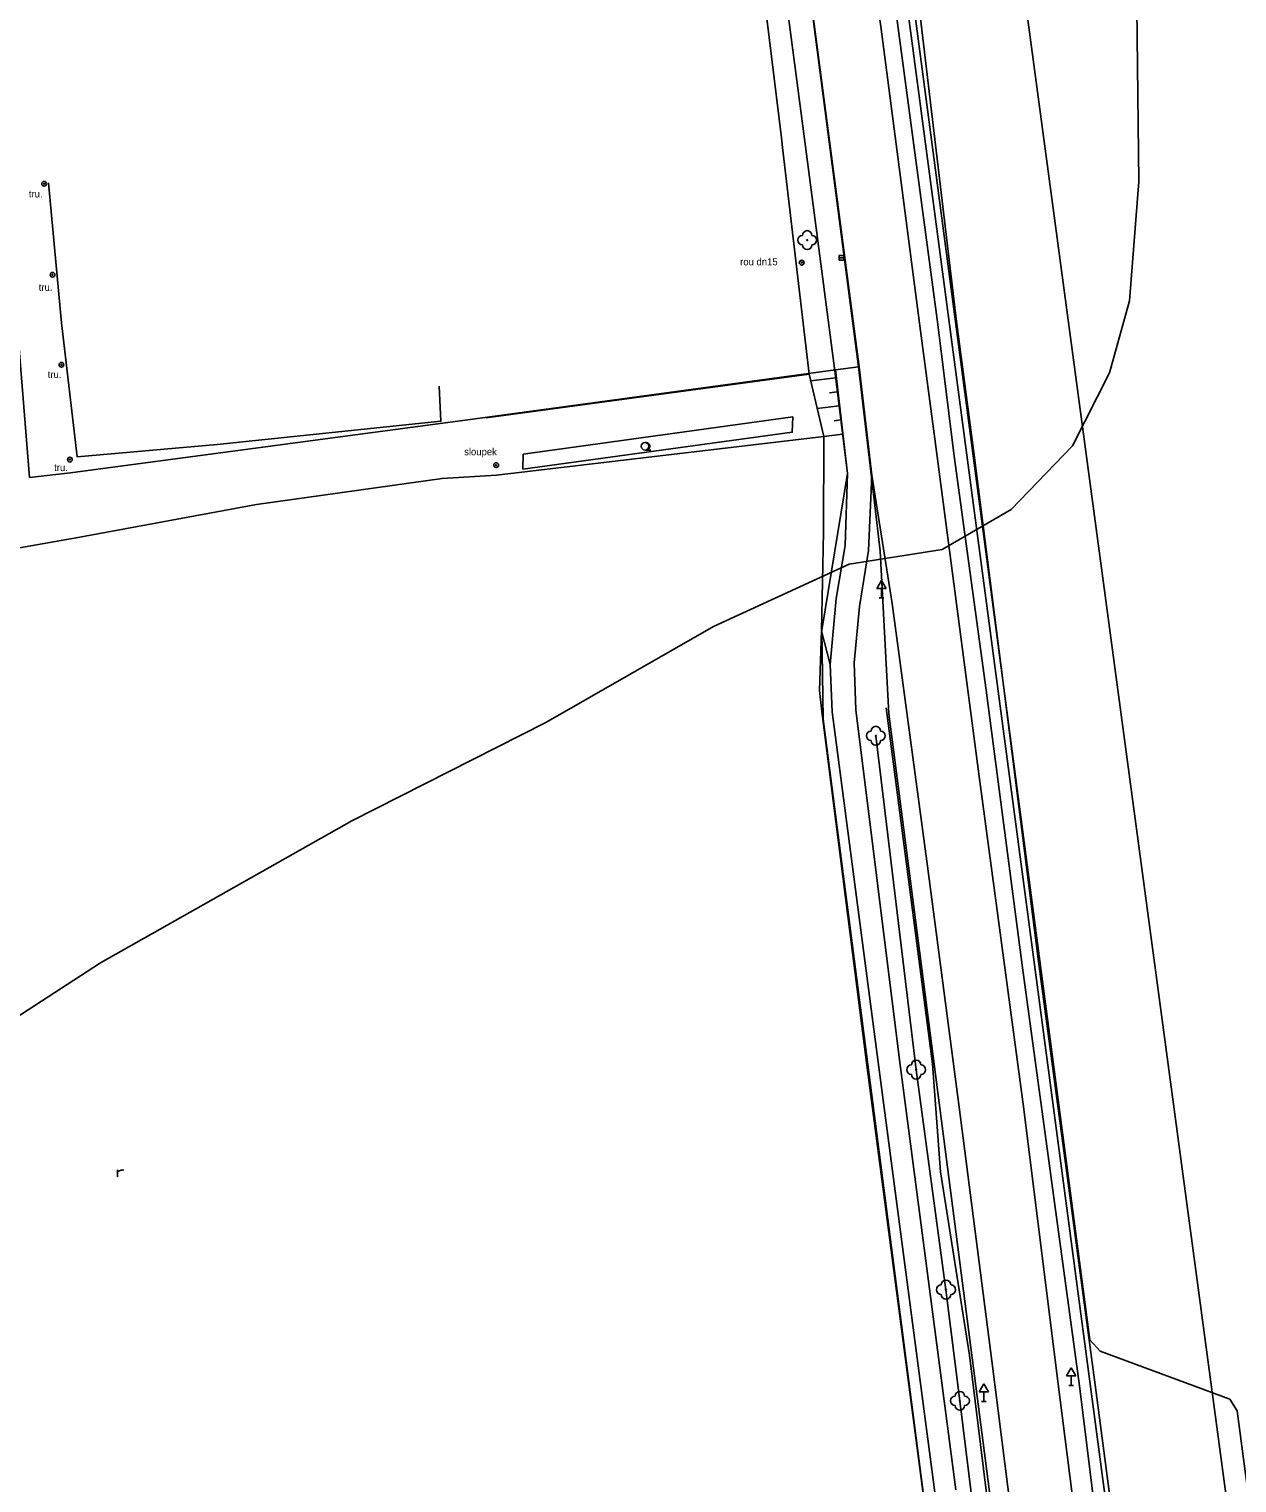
# Model space of a CAD drawing. Extents: x -555887 to -552101, y -1100251 to -1096546.
# Drawn here: x -554088.5 to -553960.9, y -1098102.3 to -1097948.7 of the extents above; entities that cross this region are included whole.
import ezdxf

# ---------------------------------------------------------------- set-up
doc = ezdxf.new("R2010")
doc.units = 0
for name, color, linetype in [('07_KANALIZACE', 7, 'Continuous'), ('07_VODOVOD', 7, 'Continuous'), ('PARCELY_silnice', 7, 'Continuous'), ('vrstevnice', 7, 'Continuous'), ('ZSST', 7, 'Continuous'), ('zájem', 7, 'Continuous')]:
    doc.layers.add(name, color=color, linetype=linetype)

msp = doc.modelspace()

# ---------------------------------------------------------------- linework, layer by layer
at = {"layer": '07_KANALIZACE'}
msp.add_lwpolyline([(-553933.89, -1098299.13), (-553960.89, -1098094.71), (-553961.69, -1098093.49), (-553975.36, -1098088.42), (-553976.47, -1098087.2), (-553997.02, -1097931.32), (-553999.16, -1097907.75), (-553999.72, -1097884.17), (-554000.63, -1097884.27), (-554001.15, -1097883.39), (-554017.16, -1097885.22), (-554171.94, -1097905.19), (-554183.71, -1097906.5), (-554193.28, -1097906.43), (-554202.55, -1097905.69), (-554209.22, -1097906.28), (-554215.09, -1097906.8), (-554226.01, -1097910.87), (-554237.13, -1097913.33)], dxfattribs=at)
at = {"layer": '07_VODOVOD'}
msp.add_lwpolyline([(-553936.18, -1098296.39), (-554003.21, -1097797.26), (-554016.58, -1097798.55), (-554021.42, -1097763.29), (-554007.81, -1097761.46), (-554017.88, -1097690.59), (-554019.47, -1097678.04), (-553931.71, -1097666.8), (-553860.51, -1097660.95), (-553851.19, -1097659.98), (-553809.18, -1097658.76), (-553772.31, -1097657.57), (-553745.69, -1097656.81), (-553714.89, -1097655.5), (-553705.57, -1097655.38), (-553663.41, -1097654.21), (-553621.83, -1097652.81), (-553564.87, -1097648.3)], dxfattribs=at)
at = {"layer": 'PARCELY_silnice'}
for points in [[(-553950.34, -1098288.41), (-554001.81, -1097900.62), (-554000.01, -1097890.44), (-554002.33, -1097872.53), (-554008.3, -1097844.49), (-554029.64, -1097687.62), (-554030.91, -1097678.33), (-554047.02, -1097559.88)], [(-554053.21, -1097604.42), (-554046.53, -1097659.36), (-554040.57, -1097685.1), (-554037.19, -1097711.74), (-554032.71, -1097743.24), (-554030.08, -1097764.38), (-554029.42, -1097766.27), (-554026.13, -1097796.62), (-554021.75, -1097825.43), (-554018.68, -1097848.98), (-554014.41, -1097881.75), (-554013.24, -1097889.61), (-554000.89, -1097984.42), (-553998.62, -1098003.87), (-553997.67, -1098021.07), (-553963.01, -1098289.11)]]:
    msp.add_lwpolyline(points, dxfattribs=at)
msp.add_lwpolyline([(-553975.92, -1098339.86), (-553969.49, -1098341.12), (-553964.35, -1098318.47), (-553963.01, -1098289.11), (-553997.67, -1098021.07), (-553998.62, -1098003.87), (-554000.89, -1097984.42), (-554003.33, -1097984.74), (-554002.07, -1097995.68), (-554004.77, -1098012.25), (-554004.64, -1098021.66), (-553970.02, -1098289.25), (-553971.01, -1098316.82)], close=True, dxfattribs=at)
at = {"layer": 'vrstevnice'}
msp.add_lwpolyline([(-554220.66, -1098097.94), (-554208.86, -1098100.05), (-554185.27, -1098101.59), (-554176.57, -1098101.45), (-554168.14, -1098099.63), (-554156.63, -1098095.69), (-554138.09, -1098086.43), (-554136.41, -1098084.88), (-554131.64, -1098082.36), (-554110.85, -1098066.77), (-554080.95, -1098047.39), (-554054.41, -1098032.37), (-554033.91, -1098021.98), (-554016.21, -1098011.87), (-554001.89, -1098005.27), (-553992.06, -1098003.72), (-553984.76, -1097999.51), (-553978.3, -1097992.77), (-553974.37, -1097985.05), (-553972.26, -1097977.47), (-553971.28, -1097964.83), (-553971.56, -1097940.4), (-553970.86, -1097921.02)], dxfattribs=at)
at = {"layer": 'ZSST'}
for p, q in [((-554011.92, -1097936.34), (-554009.04, -1097960.25)), ((-554008.91, -1097961.26), (-554009.04, -1097960.25)), ((-554002.94, -1097972.92), (-554002.44, -1097972.92)), ((-554003.4, -1097984.84), (-554003.4, -1097984.84)), ((-554004.55, -1097991.77), (-554006.09, -1097985.19)), ((-554003.31, -1097985.57), (-554005.93, -1097985.89)), ((-554003.13, -1097987.06), (-554003.94, -1097987.16)), ((-554002.94, -1097988.55), (-554005.24, -1097988.83)), ((-554002.76, -1097990.04), (-554003.47, -1097990.13)), ((-554004.55, -1097991.77), (-554039.12, -1097995.88)), ((-554002.58, -1097991.53), (-554004.55, -1097991.77)), ((-554023.43, -1097993.22), (-554023.33, -1097993.22)), ((-554023.33, -1097993.22), (-554022.83, -1097993.22)), ((-553999.82, -1098003.82), (-553999.5, -1097995.87)), ((-553998.97, -1098007.83), (-553998.47, -1098006.98)), ((-553998.97, -1098007.83), (-553997.97, -1098007.83)), ((-553998.47, -1098006.98), (-553997.97, -1098007.83)), ((-553998.47, -1098008.83), (-553998.47, -1098007.83)), ((-553998.72, -1098008.83), (-553998.22, -1098008.83)), ((-554003.88, -1098015.88), (-554004.8, -1098012.3)), ((-553978.93, -1098091.02), (-553978.43, -1098090.17)), ((-553978.93, -1098091.02), (-553977.93, -1098091.02)), ((-553978.43, -1098090.17), (-553977.93, -1098091.02)), ((-553978.43, -1098092.02), (-553978.43, -1098091.02)), ((-553988.16, -1098092.71), (-553987.66, -1098091.86)), ((-553987.66, -1098091.86), (-553987.16, -1098092.71)), ((-553978.68, -1098092.02), (-553978.18, -1098092.02)), ((-553988.16, -1098092.71), (-553987.16, -1098092.71)), ((-553987.91, -1098093.71), (-553987.41, -1098093.71)), ((-553987.66, -1098093.71), (-553987.66, -1098092.71))]:
    msp.add_line(p, q, dxfattribs=at)
for points in [[(-553988.71, -1097993.49), (-553990.53, -1097979.62), (-553994.29, -1097948.23), (-553997.94, -1097915.23), (-553998.81, -1097902.59), (-553998.52, -1097895.24), (-553994.86, -1097892.14), (-553987.27, -1097890.96), (-553987.98, -1097886.25), (-553996.36, -1097886.64), (-553999.4, -1097885.09), (-554001.76, -1097874.55)], [(-554014.9, -1097898.08), (-554013.96, -1097906.04), (-554012.3, -1097916.37), (-554009.4, -1097938.89), (-554006.77, -1097959.01), (-554003.4, -1097984.84)], [(-554004.38, -1097907.95), (-553998.53, -1097948.46), (-553994.33, -1097980.61), (-553992.57, -1097993.91)], [(-553990.78, -1097993.85), (-553992.5, -1097979.96), (-553996.76, -1097948.12), (-554002.05, -1097908.06)], [(-554004.21, -1097958.68), (-554006.85, -1097938.54), (-554009.57, -1097915.75), (-554009.89, -1097915.72)], [(-553999.5, -1097995.87), (-554000.83, -1097984.42), (-554004.21, -1097958.68)], [(-554008.91, -1097961.26), (-554006.09, -1097985.19), (-554040.22, -1097989.81)], [(-554045.19, -1097986.48), (-554044.99, -1097990.17), (-554068.61, -1097992.64), (-554083.41, -1097993.95), (-554085.05, -1097979.79), (-554086.43, -1097964.99)], [(-554152.46, -1098196.01), (-554156.99, -1098165.3), (-554161, -1098137.92), (-554165.48, -1098109.51), (-554170.05, -1098075.75), (-554174.2, -1098049.14), (-554157.63, -1098045.66), (-554138.38, -1098042.46), (-554114.45, -1098037.99), (-554118.53, -1098007.72), (-554123.48, -1097972.27), (-554107.54, -1097970.66), (-554103.52, -1097970.92), (-554100.42, -1097986.55), (-554097.93, -1098005.02), (-554083.5, -1098002.49), (-554064.47, -1097998.97), (-554044.87, -1097996.23), (-554039.12, -1097995.88)], [(-554002.31, -1098003.31), (-554002.07, -1097995.68), (-554003.4, -1097984.84)], [(-553977.31, -1098339.19), (-553975.61, -1098335.29), (-553972.59, -1098323.6), (-553971.44, -1098316.97), (-553969.88, -1098303.44), (-553969.81, -1098290.61), (-553972.17, -1098269.21), (-553975.16, -1098246.95), (-553978.59, -1098220.4), (-553983.45, -1098184.31), (-553986.7, -1098159.44), (-553989.55, -1098137.24), (-553994, -1098104), (-554000.05, -1098057.93), (-554004.75, -1098020.85), (-554005.01, -1098018.62), (-554004.8, -1098012.3), (-554004.6, -1098001.9), (-554004.55, -1097991.77)], [(-553973.87, -1098138.69), (-553979.61, -1098093.26), (-553983.51, -1098062.31), (-553988.15, -1098027.7), (-553992.57, -1097993.91)], [(-553951.2, -1098319.93), (-553951.28, -1098302.07), (-553958.7, -1098233.53), (-553961.27, -1098215.25), (-553968.42, -1098161.7), (-553973.37, -1098125.99), (-553977.56, -1098092.07), (-553983.59, -1098047.63), (-553987.39, -1098018.59), (-553990.78, -1097993.85)], [(-553988.71, -1097993.49), (-553985.58, -1098018.09), (-553981.87, -1098047.25), (-553975.9, -1098091.95), (-553971.51, -1098125.49), (-553966.51, -1098161.83), (-553959.93, -1098205.07), (-553958.71, -1098213.37), (-553956.01, -1098234), (-553950.44, -1098275.83), (-553949.64, -1098302.75), (-553950.51, -1098313.18), (-553948.45, -1098323.92)], [(-553999.5, -1097995.87), (-553997.34, -1098009.41), (-553993.61, -1098037.17), (-553990.25, -1098062.63), (-553986.8, -1098089.44), (-553984.76, -1098105.56), (-553980.36, -1098139.56)], [(-554002.31, -1098003.31), (-554003.24, -1098008.91), (-554003.88, -1098015.88), (-554003.67, -1098020.88)], [(-554001.19, -1098020.67), (-554001.35, -1098015.68), (-554000.79, -1098009.73), (-553999.82, -1098003.82)], [(-553997.98, -1098020.44), (-553993.08, -1098058.06), (-553992.23, -1098069.47), (-553989.18, -1098088.83), (-553987.4, -1098103.12), (-553982.63, -1098137.08)], [(-553992.79, -1098103.58), (-553998.8, -1098057.88), (-554003.67, -1098020.88)], [(-554001.19, -1098020.67), (-553996.57, -1098057.62), (-553990.6, -1098103.06)], [(-553999.06, -1098023.4), (-553994.8, -1098058.67), (-553991.65, -1098081.91), (-553990.18, -1098093.65), (-553988.27, -1098109.08), (-553983.19, -1098145.55)], [(-554079.15, -1098069.99), (-554079.15, -1098069.26)], [(-554079.15, -1098069.5), (-554079.04, -1098069.4), (-554078.94, -1098069.34), (-554078.78, -1098069.29), (-554078.63, -1098069.27), (-554078.48, -1098069.26)]]:
    msp.add_lwpolyline(points, dxfattribs=at)
for points in [[(-554002.94, -1097973.17), (-554002.44, -1097973.17), (-554002.44, -1097972.67), (-554002.94, -1097972.67)], [(-554036.3, -1097993.66), (-554007.82, -1097989.72), (-554007.89, -1097991.34), (-554036.33, -1097995.22)]]:
    msp.add_lwpolyline(points, close=True, dxfattribs=at)
for centre, radius in [((-554086.9, -1097965.09), 0.25), ((-554086.9, -1097965.09), 0.05), ((-554006.31, -1097971.04), 0.05), ((-554006.89, -1097973.42), 0.25), ((-554006.89, -1097973.42), 0.05), ((-554086.01, -1097974.7), 0.25), ((-554086.01, -1097974.7), 0.05), ((-554085.08, -1097984.2), 0.25), ((-554085.08, -1097984.2), 0.05), ((-554023.43, -1097992.82), 0.4), ((-554084.18, -1097994.23), 0.25), ((-554084.18, -1097994.23), 0.05), ((-554039.16, -1097994.81), 0.25), ((-554039.16, -1097994.81), 0.05), ((-553999.06, -1098023.4), 0.05), ((-553994.8, -1098058.67), 0.05), ((-553991.65, -1098081.91), 0.05), ((-553990.18, -1098093.65), 0.05)]:
    msp.add_circle(centre, radius, dxfattribs=at)
for centre, radius, start, end in [((-554006.81, -1097971.04), 0.5, 90, 270), ((-554006.31, -1097970.54), 0.5, 0, 180), ((-554005.81, -1097971.04), 0.5, 270, 90), ((-554006.31, -1097971.54), 0.5, 180, 0), ((-554023.33, -1097992.82), 0.4, 259.6952, 97.1808), ((-553999.56, -1098023.4), 0.5, 90, 270), ((-553999.06, -1098022.9), 0.5, 0, 180), ((-553998.56, -1098023.4), 0.5, 270, 90), ((-553999.06, -1098023.9), 0.5, 180, 0), ((-553995.3, -1098058.67), 0.5, 90, 270), ((-553994.8, -1098058.17), 0.5, 0, 180), ((-553994.3, -1098058.67), 0.5, 270, 90), ((-553994.8, -1098059.17), 0.5, 180, 0), ((-553992.15, -1098081.91), 0.5, 90, 270), ((-553991.65, -1098081.41), 0.5, 0, 180), ((-553991.15, -1098081.91), 0.5, 270, 90), ((-553991.65, -1098082.41), 0.5, 180, 0), ((-553990.68, -1098093.65), 0.5, 90, 270), ((-553990.18, -1098093.15), 0.5, 0, 180), ((-553990.18, -1098094.15), 0.5, 180, 0), ((-553989.68, -1098093.65), 0.5, 270, 90)]:
    msp.add_arc(centre, radius, start, end, dxfattribs=at)
at = {"layer": 'zájem'}
for points in [[(-554197.11, -1097931.27), (-554189.09, -1097981.7), (-554124.95, -1097970.9), (-554103.01, -1097968.19), (-554090.8, -1097966.7), (-554088.43, -1097996.13), (-554084.13, -1097995.62), (-554041.38, -1097989.92), (-554003.33, -1097984.74), (-554000.89, -1097984.42), (-554013.24, -1097889.61)], [(-554013.24, -1097889.61), (-554000.89, -1097984.42), (-554003.33, -1097984.74), (-554041.38, -1097989.92), (-554084.13, -1097995.62), (-554088.43, -1097996.13), (-554090.8, -1097966.7), (-554103.01, -1097968.19), (-554124.95, -1097970.9), (-554189.09, -1097981.7), (-554197.11, -1097931.27)]]:
    msp.add_lwpolyline(points, dxfattribs=at)

# ---------------------------------------------------------------- texts
at = {"layer": 'ZSST'}
for s, p in [('tru.', (-554088.51, -1097966.53)), ('rou dn15', (-554013.39, -1097973.7)), ('tru.', (-554087.47, -1097976.4)), ('tru.', (-554086.52, -1097985.6)), ('sloupek', (-554042.54, -1097993.77)), ('tru.', (-554085.84, -1097995.44))]:
    msp.add_text(s, height=0.75, dxfattribs=at).set_placement(p)

doc.saveas('drawing.dxf')
